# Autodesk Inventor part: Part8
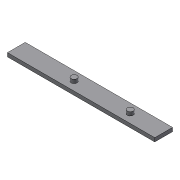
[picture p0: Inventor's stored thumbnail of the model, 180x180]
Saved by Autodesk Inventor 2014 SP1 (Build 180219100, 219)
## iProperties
Created: 2014-01
Part Number: Part8
Material: 一般
Document SubType Name: Modeling
Designer: Hashimoto
Density: 1 g/cm^3
Appearance: 既定
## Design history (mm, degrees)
sketch "スケッチ3"
  geometry: L1 (-150, -19.249)-(150, -19.249); L2 (150, -19.249)-(150, 19.249); L3 (150, 19.249)-(-150, 19.249); L4 (-150, 19.249)-(-150, -19.249); 3 further points
  constraints: 8 end point, 2 midpoint, 2 parallel, 1 horizontal, 1 horizontal alignment, 1 perpendicular, 1 vertical alignment
  dimensions: "d6" = 300 distance of L2.end L3.end
extrude "押し出し3" new body sketch "スケッチ3" distance "d7" = 10; taper "d8" = 0 deg
sketch "スケッチ4"
  geometry: C1 r 7.937 at (-76.2, 0); C2 r 7.937 at (76.2, 0); 1 further point
  constraints: 2 centre point, 2 horizontal alignment
  dimensions: "d12" = 152.4 distance of C2.centre C1.centre; "d13" = 76.2 distance of point (0, 0) C1.centre (= 0.5 x d12)
extrude "押し出し4" join sketch "スケッチ4" distance "d9" = 10; taper "d10" = 0 deg
node "ソリッド3"
